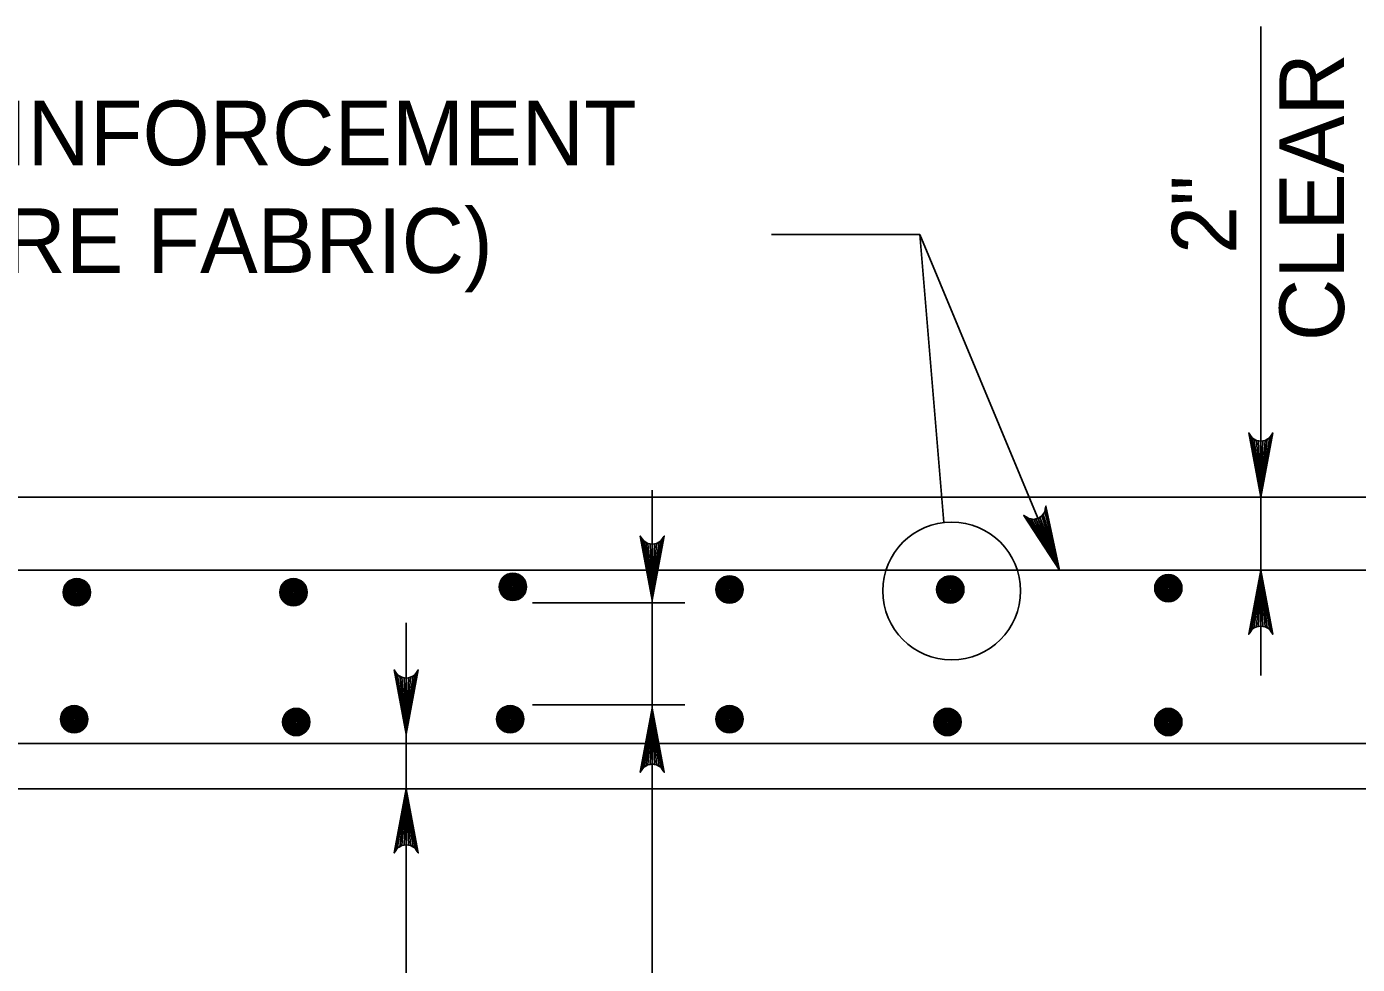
# Model space of a CAD drawing. Extents: x -6420 to 49575, y -4552 to 11624.
# Drawn here: x 5119.6 to 5322.5, y 2262.8 to 2405.8 of the extents above; entities that cross this region are included whole.
import ezdxf

# ---------------------------------------------------------------- set-up
doc = ezdxf.new("R2010")
doc.units = 0
doc.layers.add('1', color=7, linetype='Continuous')

msp = doc.modelspace()

# ---------------------------------------------------------------- linework, layer by layer
at = {"layer": '1'}
for p, q in [((5307.73, 2405.78), (5307.73, 2306.9)), ((5255.79, 2374.07), (5233.15, 2374.07)), ((5255.79, 2374.07), (5277.05, 2322.95)), ((5255.79, 2374.07), (5259.41, 2330.2)), ((5214.98, 2335.15), (5214.98, 2232.34)), ((5010.09, 2334.07), (5410.1, 2334.07)), ((5000.06, 2322.95), (5423.01, 2322.95)), ((5260.62, 2319.77), (5260.62, 2319.77)), ((5196.72, 2317.96), (5219.92, 2317.96)), ((5177.48, 2314.91), (5177.48, 2209.51)), ((5196.72, 2302.4), (5219.92, 2302.4)), ((5435.1, 2296.51), (4985.09, 2296.51)), ((5443.43, 2289.62), (4976.75, 2289.62))]:
    msp.add_line(p, q, dxfattribs=at)
for points in [[(5307.73, 2334.07), (5305.9, 2343.85), (5306.16, 2343.48), (5306.42, 2343.1), (5306.75, 2342.9), (5307.08, 2342.71), (5307.41, 2342.65), (5307.73, 2342.6), (5308.06, 2342.65), (5308.39, 2342.71), (5308.72, 2342.9), (5309.05, 2343.1), (5309.31, 2343.48), (5309.57, 2343.85), (5307.73, 2334.07), (5309.31, 2343.48), (5309.05, 2343.1), (5307.73, 2334.07), (5308.72, 2342.9), (5308.39, 2342.71), (5307.73, 2334.07), (5308.06, 2342.65), (5307.73, 2342.6), (5307.73, 2334.07), (5307.41, 2342.65), (5307.08, 2342.71), (5307.73, 2334.07), (5306.75, 2342.9), (5306.42, 2343.1), (5307.73, 2334.07), (5306.16, 2343.48)], [(5277.05, 2322.95), (5271.6, 2331.28), (5271.99, 2331.04), (5272.37, 2330.79), (5272.75, 2330.74), (5273.13, 2330.68), (5273.45, 2330.76), (5273.78, 2330.83), (5274.06, 2331.01), (5274.34, 2331.19), (5274.57, 2331.49), (5274.8, 2331.8), (5274.89, 2332.25), (5274.99, 2332.69), (5277.05, 2322.95), (5274.89, 2332.25), (5274.8, 2331.8), (5277.05, 2322.95), (5274.57, 2331.49), (5274.34, 2331.19), (5277.05, 2322.95), (5274.06, 2331.01), (5273.78, 2330.83), (5277.05, 2322.95), (5273.45, 2330.76), (5273.13, 2330.68), (5277.05, 2322.95), (5272.75, 2330.74), (5272.37, 2330.79), (5277.05, 2322.95), (5271.99, 2331.04)], [(5214.98, 2318.35), (5213.15, 2328.14), (5213.41, 2327.76), (5213.67, 2327.38), (5214, 2327.19), (5214.33, 2326.99), (5214.66, 2326.94), (5214.98, 2326.88), (5215.31, 2326.94), (5215.64, 2326.99), (5215.97, 2327.19), (5216.3, 2327.38), (5216.56, 2327.76), (5216.82, 2328.14), (5214.98, 2318.35), (5216.56, 2327.76), (5216.3, 2327.38), (5214.98, 2318.35), (5215.97, 2327.19), (5215.64, 2326.99), (5214.98, 2318.35), (5215.31, 2326.94), (5214.98, 2326.88), (5214.98, 2318.35), (5214.66, 2326.94), (5214.33, 2326.99), (5214.98, 2318.35), (5214, 2327.19), (5213.67, 2327.38), (5214.98, 2318.35), (5213.41, 2327.76)], [(5307.73, 2322.95), (5309.57, 2313.17), (5309.31, 2313.55), (5309.05, 2313.92), (5308.72, 2314.12), (5308.39, 2314.31), (5308.06, 2314.37), (5307.73, 2314.42), (5307.41, 2314.37), (5307.08, 2314.31), (5306.75, 2314.12), (5306.42, 2313.92), (5306.16, 2313.55), (5305.9, 2313.17), (5307.73, 2322.95), (5306.16, 2313.55), (5306.42, 2313.92), (5307.73, 2322.95), (5306.75, 2314.12), (5307.08, 2314.31), (5307.73, 2322.95), (5307.41, 2314.37), (5307.73, 2314.42), (5307.73, 2322.95), (5308.06, 2314.37), (5308.39, 2314.31), (5307.73, 2322.95), (5308.72, 2314.12), (5309.05, 2313.92), (5307.73, 2322.95), (5309.31, 2313.55)], [(5177.48, 2297.95), (5175.64, 2307.74), (5175.9, 2307.36), (5176.17, 2306.98), (5176.49, 2306.79), (5176.82, 2306.6), (5177.15, 2306.54), (5177.48, 2306.48), (5177.81, 2306.54), (5178.13, 2306.6), (5178.46, 2306.79), (5178.79, 2306.98), (5179.05, 2307.36), (5179.31, 2307.74), (5177.48, 2297.95), (5179.05, 2307.36), (5178.79, 2306.98), (5177.48, 2297.95), (5178.46, 2306.79), (5178.13, 2306.6), (5177.48, 2297.95), (5177.81, 2306.54), (5177.48, 2306.48), (5177.48, 2297.95), (5177.15, 2306.54), (5176.82, 2306.6), (5177.48, 2297.95), (5176.49, 2306.79), (5176.17, 2306.98), (5177.48, 2297.95), (5175.9, 2307.36)], [(5214.98, 2301.92), (5216.82, 2292.13), (5216.56, 2292.51), (5216.3, 2292.89), (5215.97, 2293.08), (5215.64, 2293.28), (5215.31, 2293.33), (5214.98, 2293.39), (5214.66, 2293.33), (5214.33, 2293.28), (5214, 2293.08), (5213.67, 2292.89), (5213.41, 2292.51), (5213.15, 2292.13), (5214.98, 2301.92), (5213.41, 2292.51), (5213.67, 2292.89), (5214.98, 2301.92), (5214, 2293.08), (5214.33, 2293.28), (5214.98, 2301.92), (5214.66, 2293.33), (5214.98, 2293.39), (5214.98, 2301.92), (5215.31, 2293.33), (5215.64, 2293.28), (5214.98, 2301.92), (5215.97, 2293.08), (5216.3, 2292.89), (5214.98, 2301.92), (5216.56, 2292.51)], [(5177.48, 2289.62), (5179.31, 2279.83), (5179.05, 2280.21), (5178.79, 2280.59), (5178.46, 2280.78), (5178.13, 2280.98), (5177.81, 2281.03), (5177.48, 2281.09), (5177.15, 2281.03), (5176.82, 2280.98), (5176.49, 2280.78), (5176.17, 2280.59), (5175.9, 2280.21), (5175.64, 2279.83), (5177.48, 2289.62), (5175.9, 2280.21), (5176.17, 2280.59), (5177.48, 2289.62), (5176.49, 2280.78), (5176.82, 2280.98), (5177.48, 2289.62), (5177.15, 2281.03), (5177.48, 2281.09), (5177.48, 2289.62), (5177.81, 2281.03), (5178.13, 2280.98), (5177.48, 2289.62), (5178.46, 2280.78), (5178.79, 2280.59), (5177.48, 2289.62), (5179.05, 2280.21)]]:
    msp.add_lwpolyline(points, dxfattribs=at)
for centre, radius in [((5260.62, 2319.77), 10.5), ((5127.28, 2319.56), 2.08), ((5127.28, 2319.56), 1.94), ((5127.28, 2319.56), 1.79), ((5127.28, 2319.56), 1.64), ((5127.28, 2319.56), 1.49), ((5127.28, 2319.56), 1.34), ((5127.28, 2319.56), 1.2), ((5127.28, 2319.56), 1.05), ((5160.3, 2319.56), 2.08), ((5160.3, 2319.56), 1.94), ((5160.3, 2319.56), 1.79), ((5160.3, 2319.56), 1.64), ((5160.3, 2319.56), 1.49), ((5160.3, 2319.56), 1.34), ((5160.3, 2319.56), 1.2), ((5160.3, 2319.56), 1.05), ((5193.74, 2320.4), 2.08), ((5193.74, 2320.4), 1.94), ((5193.74, 2320.4), 1.79), ((5193.74, 2320.4), 1.64), ((5193.74, 2320.4), 1.49), ((5193.74, 2320.4), 1.34), ((5193.74, 2320.4), 1.2), ((5193.74, 2320.4), 1.05), ((5193.74, 2320.4), 0.9), ((5193.74, 2320.4), 0.752), ((5193.74, 2320.4), 0.604), ((5193.74, 2320.4), 0.456), ((5193.74, 2320.4), 0.308), ((5193.74, 2320.4), 0.16), ((5226.76, 2319.98), 2.08), ((5226.76, 2319.98), 1.94), ((5226.76, 2319.98), 1.79), ((5226.76, 2319.98), 1.64), ((5226.76, 2319.98), 1.49), ((5226.76, 2319.98), 1.34), ((5226.76, 2319.98), 1.2), ((5226.76, 2319.98), 1.05), ((5226.76, 2319.98), 0.9), ((5226.76, 2319.98), 0.752), ((5226.76, 2319.98), 0.604), ((5260.41, 2319.98), 2.08), ((5260.41, 2319.98), 1.94), ((5260.41, 2319.98), 1.79), ((5260.41, 2319.98), 1.64), ((5260.41, 2319.98), 1.49), ((5260.41, 2319.98), 1.34), ((5260.41, 2319.98), 1.2), ((5260.41, 2319.98), 1.05), ((5260.41, 2319.98), 0.9), ((5260.41, 2319.98), 0.752), ((5260.41, 2319.98), 0.604), ((5293.64, 2320.19), 2.08), ((5293.64, 2320.19), 1.94), ((5293.64, 2320.19), 1.79), ((5293.64, 2320.19), 1.64), ((5293.64, 2320.19), 1.49), ((5293.64, 2320.19), 1.34), ((5293.64, 2320.19), 1.2), ((5293.64, 2320.19), 1.05), ((5293.64, 2320.19), 0.9), ((5293.64, 2320.19), 0.752), ((5293.64, 2320.19), 0.604), ((5293.64, 2320.19), 0.456), ((5127.28, 2319.56), 0.9), ((5127.28, 2319.56), 0.752), ((5127.28, 2319.56), 0.604), ((5127.28, 2319.56), 0.456), ((5127.28, 2319.56), 0.308), ((5127.28, 2319.56), 0.16), ((5160.3, 2319.56), 0.9), ((5160.3, 2319.56), 0.752), ((5160.3, 2319.56), 0.604), ((5160.3, 2319.56), 0.456), ((5160.3, 2319.56), 0.308), ((5160.3, 2319.56), 0.16), ((5226.76, 2319.98), 0.456), ((5226.76, 2319.98), 0.308), ((5226.76, 2319.98), 0.16), ((5260.41, 2319.98), 0.456), ((5260.41, 2319.98), 0.308), ((5260.41, 2319.98), 0.16), ((5293.64, 2320.19), 0.308), ((5293.64, 2320.19), 0.16), ((5126.86, 2300.21), 2.08), ((5193.32, 2300.21), 2.08), ((5226.76, 2300.21), 2.08), ((5126.86, 2300.21), 1.94), ((5126.86, 2300.21), 1.79), ((5126.86, 2300.21), 1.64), ((5126.86, 2300.21), 1.49), ((5126.86, 2300.21), 1.34), ((5126.86, 2300.21), 1.2), ((5126.86, 2300.21), 1.05), ((5126.86, 2300.21), 0.9), ((5126.86, 2300.21), 0.752), ((5126.86, 2300.21), 0.604), ((5126.86, 2300.21), 0.456), ((5126.86, 2300.21), 0.308), ((5126.86, 2300.21), 0.16), ((5160.72, 2299.79), 2.08), ((5160.72, 2299.79), 1.94), ((5160.72, 2299.79), 1.79), ((5160.72, 2299.79), 1.64), ((5160.72, 2299.79), 1.49), ((5160.72, 2299.79), 1.34), ((5160.72, 2299.79), 1.2), ((5160.72, 2299.79), 1.05), ((5160.72, 2299.79), 0.9), ((5160.72, 2299.79), 0.752), ((5160.72, 2299.79), 0.604), ((5160.72, 2299.79), 0.456), ((5193.32, 2300.21), 1.94), ((5193.32, 2300.21), 1.79), ((5193.32, 2300.21), 1.64), ((5193.32, 2300.21), 1.49), ((5193.32, 2300.21), 1.34), ((5193.32, 2300.21), 1.2), ((5193.32, 2300.21), 1.05), ((5193.32, 2300.21), 0.9), ((5193.32, 2300.21), 0.752), ((5193.32, 2300.21), 0.604), ((5193.32, 2300.21), 0.456), ((5193.32, 2300.21), 0.308), ((5193.32, 2300.21), 0.16), ((5226.76, 2300.21), 1.94), ((5226.76, 2300.21), 1.79), ((5226.76, 2300.21), 1.64), ((5226.76, 2300.21), 1.49), ((5226.76, 2300.21), 1.34), ((5226.76, 2300.21), 1.2), ((5226.76, 2300.21), 1.05), ((5226.76, 2300.21), 0.9), ((5226.76, 2300.21), 0.752), ((5226.76, 2300.21), 0.604), ((5226.76, 2300.21), 0.456), ((5226.76, 2300.21), 0.308), ((5226.76, 2300.21), 0.16), ((5259.99, 2299.79), 2.08), ((5259.99, 2299.79), 1.94), ((5259.99, 2299.79), 1.79), ((5259.99, 2299.79), 1.64), ((5259.99, 2299.79), 1.49), ((5259.99, 2299.79), 1.34), ((5259.99, 2299.79), 1.2), ((5259.99, 2299.79), 1.05), ((5259.99, 2299.79), 0.9), ((5259.99, 2299.79), 0.752), ((5259.99, 2299.79), 0.604), ((5259.99, 2299.79), 0.456), ((5293.64, 2299.79), 2.08), ((5293.64, 2299.79), 1.94), ((5293.64, 2299.79), 1.79), ((5293.64, 2299.79), 1.64), ((5293.64, 2299.79), 1.49), ((5293.64, 2299.79), 1.34), ((5293.64, 2299.79), 1.2), ((5293.64, 2299.79), 1.05), ((5293.64, 2299.79), 0.9), ((5293.64, 2299.79), 0.752), ((5293.64, 2299.79), 0.604), ((5293.64, 2299.79), 0.456), ((5160.72, 2299.79), 0.308), ((5160.72, 2299.79), 0.16), ((5259.99, 2299.79), 0.308), ((5259.99, 2299.79), 0.16), ((5293.64, 2299.79), 0.308), ((5293.64, 2299.79), 0.16)]:
    msp.add_circle(centre, radius, dxfattribs=at)

# ---------------------------------------------------------------- texts
for s, p in [('CLEAR', (5320.42, 2357.83)), ('2"', (5304.01, 2371.12))]:
    msp.add_text(s, height=9.843, rotation=90, dxfattribs=at).set_placement(p)
for s, p in [('TOP MAT REINFORCEMENT', (5035.65, 2384.65)), ('(WELDED WIRE FABRIC)', (5035.65, 2368.24))]:
    msp.add_text(s, height=9.8425, dxfattribs=at).set_placement(p)

doc.saveas('drawing.dxf')
